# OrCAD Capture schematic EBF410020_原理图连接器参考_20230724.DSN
size A3; title: 野火_ZYNQ7010核心板_原理图; rev: V1.1; note: BTB Connector; note: https://yehuosm.tmall.com
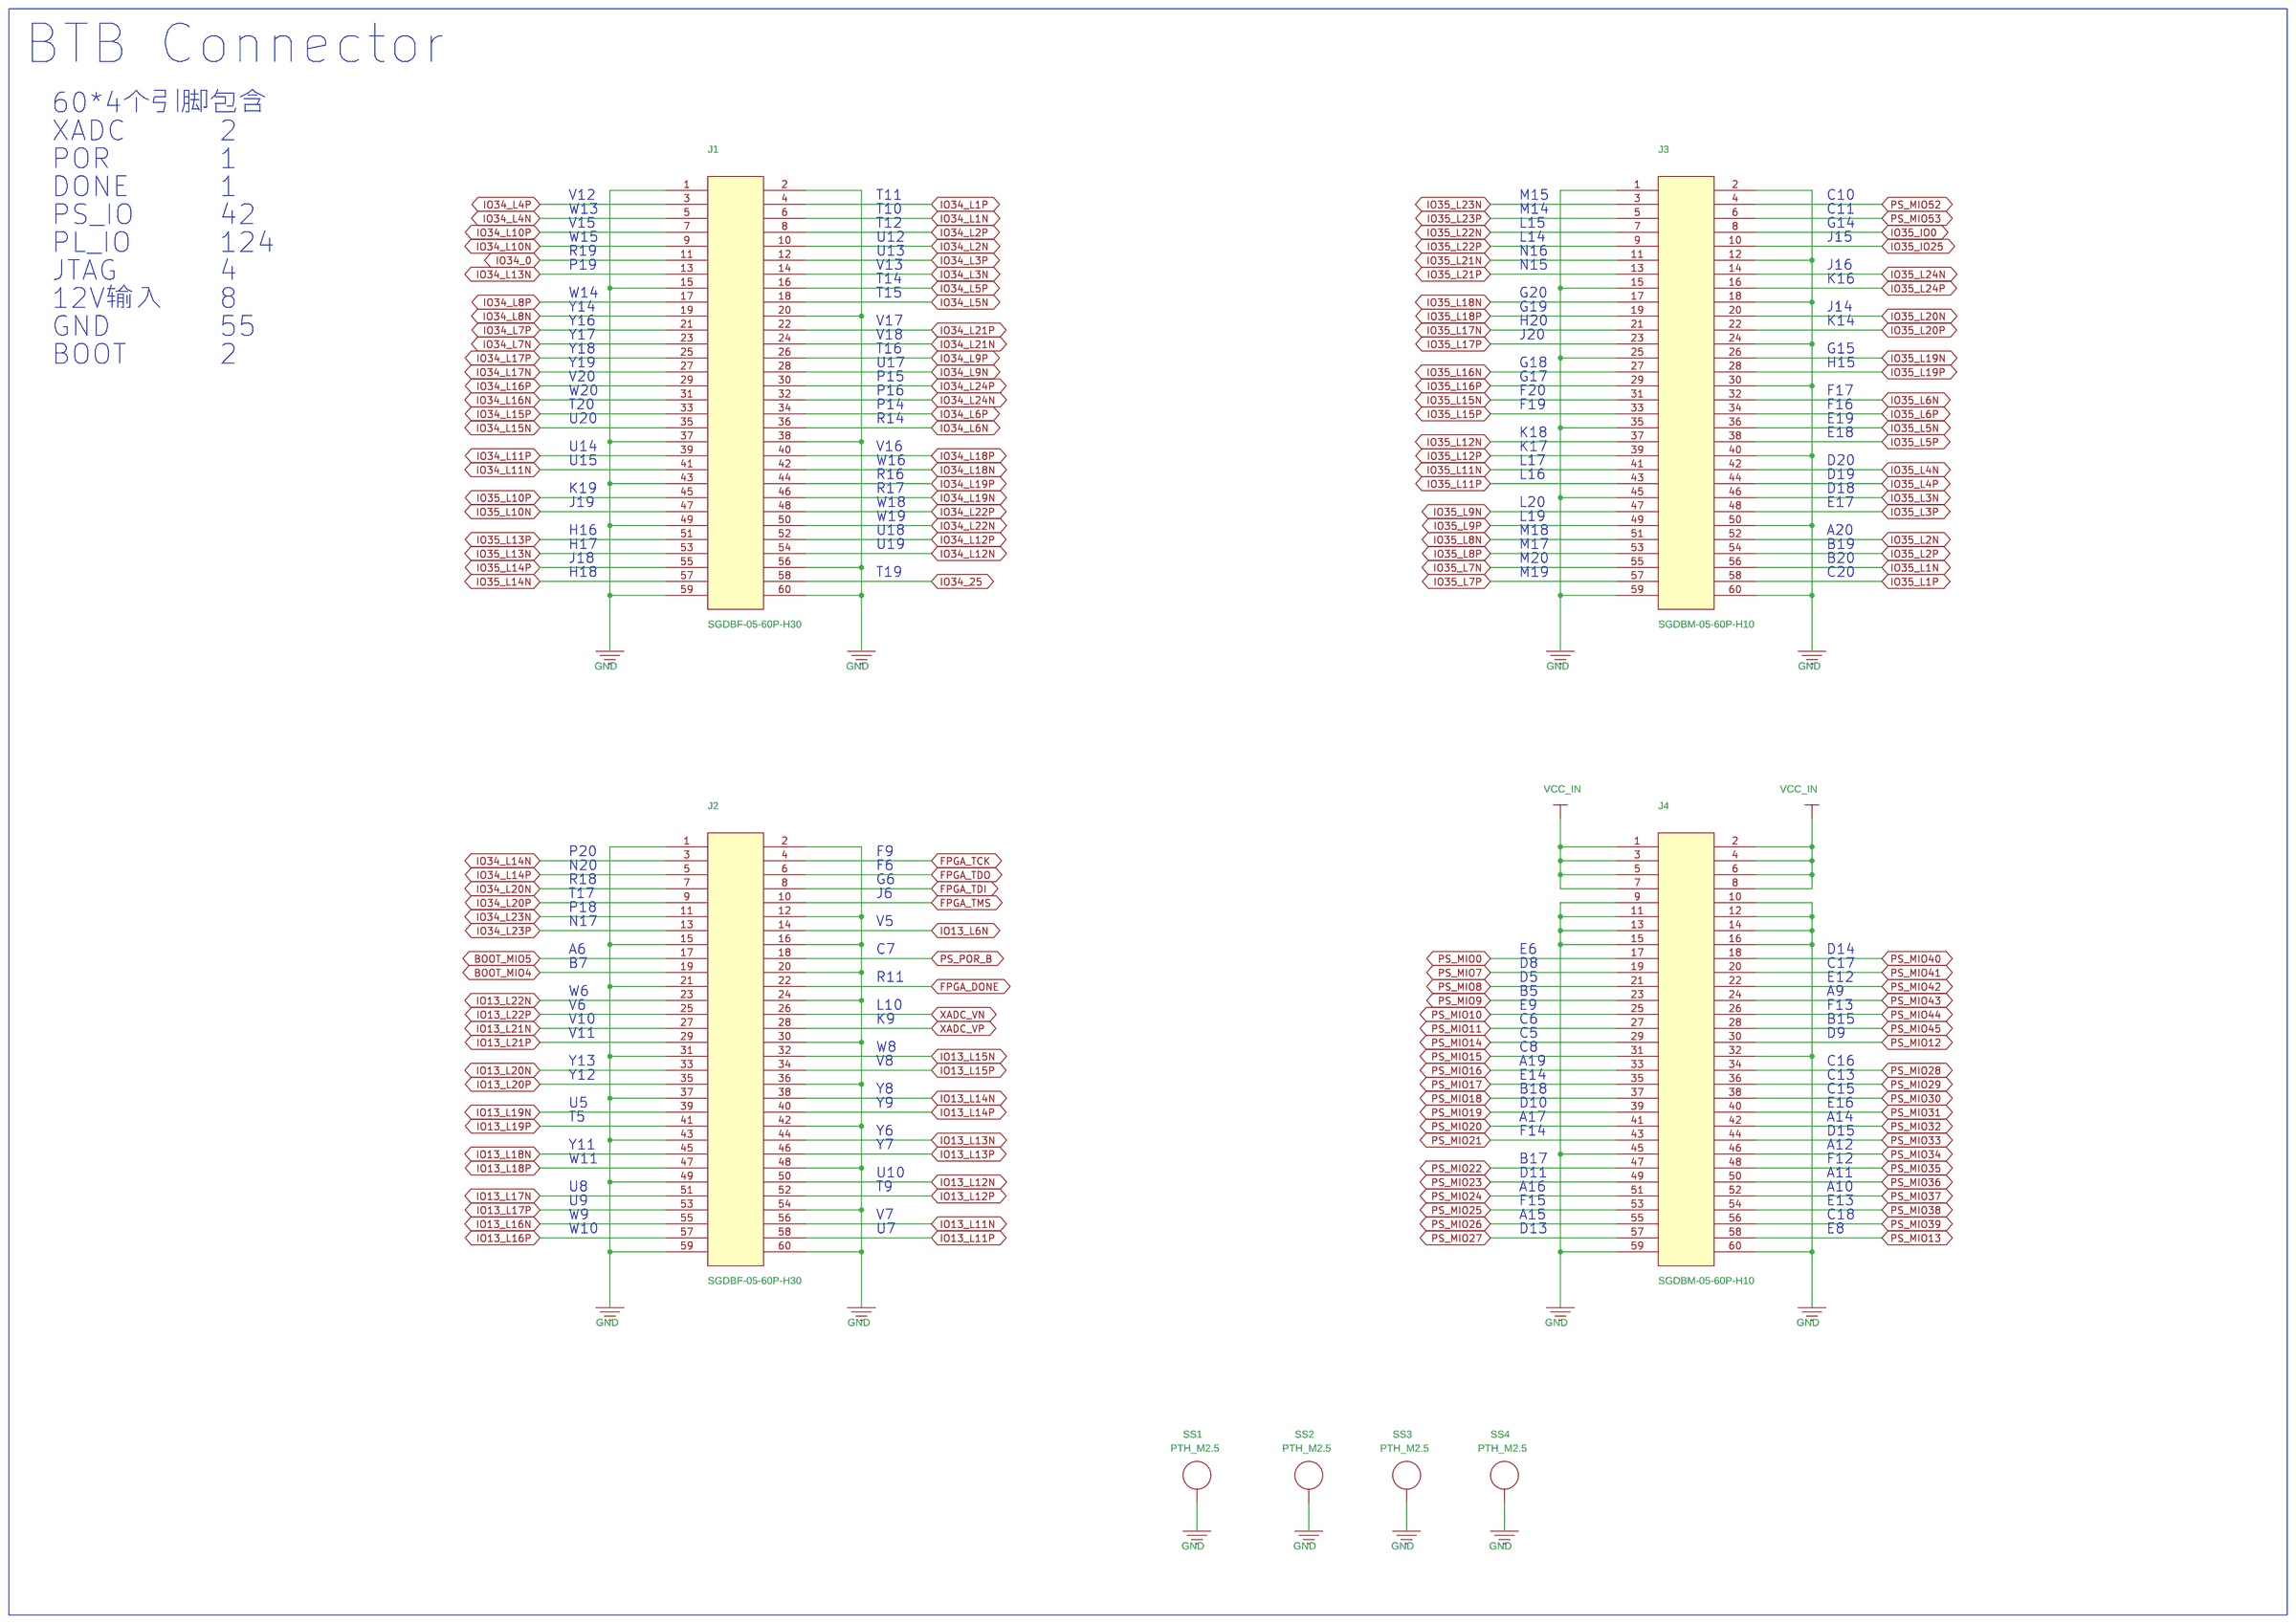
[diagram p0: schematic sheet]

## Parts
J1  SGDBF-05-60P-H30  [BTB_2X30_0P5_F]
J2  SGDBF-05-60P-H30  [BTB_2X30_0P5_F]
J3  SGDBM-05-60P-H10  [BTB_2x30_0p5_M]
J4  SGDBM-05-60P-H10  [BTB_2x30_0p5_M]
SS1  PTH_M2.5  [SMTSO-M2r5-Hole]
SS2  PTH_M2.5  [SMTSO-M2r5-Hole]
SS3  PTH_M2.5  [SMTSO-M2r5-Hole]
SS4  PTH_M2.5  [SMTSO-M2r5-Hole]

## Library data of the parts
J1 J2 = 2X30PIN: 备注: 赛灵思ZYNQ7010，GD32系列板卡; 规格: 0.5mm BTB母座2*30P 双槽 立贴式 合高4.0mm; 规格书: 山谷道_双槽板对板公母立贴式0_5mm.pdf; 类别: BTB连接器; 品牌: 山谷道; 生命周期: 量产; 条码: EBFCIS230705115421
J3 J4 = 2X30PIN: 备注: 赛灵思ZYNQ7010，GD32系列BTB核心板; 规格: 0.5mm BTB公座2*30P 双槽 立贴式 合高4.0mm; 规格书: 山谷道_双槽板对板公母立贴式0_5mm.pdf; 类别: BTB连接器; 品牌: 山谷道; 生命周期: 量产; 条码: EBFCIS230705120008
SS1-SS4 = SPACER: 规格: M2.5螺丝孔 有铜 搭配SMTSO25贴片螺母使用; 类别: M2.5螺丝孔; 品牌: 野火; 条码: EBFCIS230202105906

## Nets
GND: J1.1 J1.2 J1.15 J1.20 J1.37 J1.38 J1.43 J1.49 J1.56 J1.59 J1.60 J2.1 J2.2 J2.12 J2.15 J2.16 J2.20 J2.21 J2.24 J2.30 J2.31 J2.36 J2.37 J2.42 J2.43 J2.48 J2.49 J2.54 J2.59 J2.60 J3.1 J3.2 J3.12 J3.15 J3.18 J3.24 J3.25 J3.30 J3.35 J3.40 J3.45 J3.50 J3.59 J3.60 J4.9 J4.10 J4.11 J4.12 J4.13 J4.14 J4.15 J4.16 J4.32 J4.45 J4.59 J4.60 SS1.1(NC) SS2.1(NC) SS3.1(NC) SS4.1(NC)
VCC_IN: J4.1 J4.2 J4.3 J4.4 J4.5 J4.6 J4.7 J4.8
BOOT_MIO4: J2.19
BOOT_MIO5: J2.17
FPGA_DONE: J2.22
FPGA_TCK: J2.4
FPGA_TDI: J2.8
FPGA_TDO: J2.6
FPGA_TMS: J2.10
IO13_L6N: J2.14
IO13_L11N: J2.56
IO13_L11P: J2.58
IO13_L12N: J2.50
IO13_L12P: J2.52
IO13_L13N: J2.44
IO13_L13P: J2.46
IO13_L14N: J2.38
IO13_L14P: J2.40
IO13_L15N: J2.32
IO13_L15P: J2.34
IO13_L16N: J2.55
IO13_L16P: J2.57
IO13_L17N: J2.51
IO13_L17P: J2.53
IO13_L18N: J2.45
IO13_L18P: J2.47
IO13_L19N: J2.39
IO13_L19P: J2.41
IO13_L20N: J2.33
IO13_L20P: J2.35
IO13_L21N: J2.27
IO13_L21P: J2.29
IO13_L22N: J2.23
IO13_L22P: J2.25
IO34_0: J1.11
IO34_25: J1.58
IO34_L1N: J1.6
IO34_L1P: J1.4
IO34_L2N: J1.10
IO34_L2P: J1.8
IO34_L3N: J1.14
IO34_L3P: J1.12
IO34_L4N: J1.5
IO34_L4P: J1.3
IO34_L5N: J1.18
IO34_L5P: J1.16
IO34_L6N: J1.36
IO34_L6P: J1.34
IO34_L7N: J1.23
IO34_L7P: J1.21
IO34_L8N: J1.19
IO34_L8P: J1.17
IO34_L9N: J1.28
IO34_L9P: J1.26
IO34_L10N: J1.9
IO34_L10P: J1.7
IO34_L11N: J1.41
IO34_L11P: J1.39
IO34_L12N: J1.54
IO34_L12P: J1.52
IO34_L13N: J1.13
IO34_L14N: J2.3
IO34_L14P: J2.5
IO34_L15N: J1.35
IO34_L15P: J1.33
IO34_L16N: J1.31
IO34_L16P: J1.29
IO34_L17N: J1.27
IO34_L17P: J1.25
IO34_L18N: J1.42
IO34_L18P: J1.40
IO34_L19N: J1.46
IO34_L19P: J1.44
IO34_L20N: J2.7
IO34_L20P: J2.9
IO34_L21N: J1.24
IO34_L21P: J1.22
IO34_L22N: J1.50
IO34_L22P: J1.48
IO34_L23N: J2.11
IO34_L23P: J2.13
IO34_L24N: J1.32
IO34_L24P: J1.30
IO35_IO0: J3.8
IO35_IO25: J3.10
IO35_L1N: J3.56
IO35_L1P: J3.58
IO35_L2N: J3.52
IO35_L2P: J3.54
IO35_L3N: J3.46
IO35_L3P: J3.48
IO35_L4N: J3.42
IO35_L4P: J3.44
IO35_L5N: J3.36
IO35_L5P: J3.38
IO35_L6N: J3.32
IO35_L6P: J3.34
IO35_L7N: J3.55
IO35_L7P: J3.57
IO35_L8N: J3.51
IO35_L8P: J3.53
IO35_L9N: J3.47
IO35_L9P: J3.49
IO35_L10N: J1.47
IO35_L10P: J1.45
IO35_L11N: J3.41
IO35_L11P: J3.43
IO35_L12N: J3.37
IO35_L12P: J3.39
IO35_L13N: J1.53
IO35_L13P: J1.51
IO35_L14N: J1.57
IO35_L14P: J1.55
IO35_L15N: J3.31
IO35_L15P: J3.33
IO35_L16N: J3.27
IO35_L16P: J3.29
IO35_L17N: J3.21
IO35_L17P: J3.23
IO35_L18N: J3.17
IO35_L18P: J3.19
IO35_L19N: J3.26
IO35_L19P: J3.28
IO35_L20N: J3.20
IO35_L20P: J3.22
IO35_L21N: J3.11
IO35_L21P: J3.13
IO35_L22N: J3.7
IO35_L22P: J3.9
IO35_L23N: J3.3
IO35_L23P: J3.5
IO35_L24N: J3.14
IO35_L24P: J3.16
PS_MIO0: J4.17
PS_MIO7: J4.19
PS_MIO8: J4.21
PS_MIO9: J4.23
PS_MIO10: J4.25
PS_MIO11: J4.27
PS_MIO12: J4.30
PS_MIO13: J4.58
PS_MIO14: J4.29
PS_MIO15: J4.31
PS_MIO16: J4.33
PS_MIO17: J4.35
PS_MIO18: J4.37
PS_MIO19: J4.39
PS_MIO20: J4.41
PS_MIO21: J4.43
PS_MIO22: J4.47
PS_MIO23: J4.49
PS_MIO24: J4.51
PS_MIO25: J4.53
PS_MIO26: J4.55
PS_MIO27: J4.57
PS_MIO28: J4.34
PS_MIO29: J4.36
PS_MIO30: J4.38
PS_MIO31: J4.40
PS_MIO32: J4.42
PS_MIO33: J4.44
PS_MIO34: J4.46
PS_MIO35: J4.48
PS_MIO36: J4.50
PS_MIO37: J4.52
PS_MIO38: J4.54
PS_MIO39: J4.56
PS_MIO40: J4.18
PS_MIO41: J4.20
PS_MIO42: J4.22
PS_MIO43: J4.24
PS_MIO44: J4.26
PS_MIO45: J4.28
PS_MIO52: J3.4
PS_MIO53: J3.6
PS_POR_B: J2.18
XADC_VN: J2.26
XADC_VP: J2.28

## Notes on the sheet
- BTB Connector
- 60*4个引脚包含
- XADC
- 2
- POR
- 1
- DONE
- 1
- V12
- T11
- M15
- C10
- PS_IO
- 42
- W13
- T10
- M14
- C11
- V15
- T12
- L15
- G14
- PL_IO
- 124
- R19
- W15
- U12
- U13
- L14
- N16
- J15
- JTAG
- 4
- P19
- V13
- N15
- J16
- T14
- K16
- 12V输入
- 8
- W14
- T15
- G20
- Y14
- G19
- J14
- GND
- 55
- Y16
- V17
- H20
- K14
- BOOT
- 2
- Y17
- Y18
- T16
- V18
- J20
- G15
- Y19
- U17
- G18
- H15
- V20
- P15
- G17
- W20
- P16
- F20
- F17
- T20
- P14
- F19
- F16
- U20
- R14
- K18
- E18
- E19
- U14
- V16
- K17
- U15
- W16
- L17
- D20
- R16
- L16
- D19
- K19
- R17
- D18
- J19
- W18
- L20
- E17
- H16
- U18
- W19
- L19
- M18
- A20
- H17
- U19
- M17
- B19
- J18
- M20
- B20
- H18
- T19
- M19
- C20
- P20
- F9
- N20
- F6
- R18
- T17
- G6
- J6
- P18
- N17
- V5
- A6
- C7
- E6
- D14
- B7
- D8
- C17
- W6
- R11
- B5
- D5
- A9
- E12
- V6
- L10
- E9
- F13
- V10
- K9
- C6
- B15
- V11
- C5
- D9
- W8
- C8
- Y12
- Y13
- V8
- A19
- E14
- C13
- C16
- Y8
- B18
- C15
- U5
- Y9
- D10
- E16
- T5
- A17
- A14
- Y6
- F14
- D15
- Y11
- Y7
- A12
- W11
- U10
- B17
- D11
- A11
- F12
- U8
- T9
- A16
- A10
- U9
- F15
- E13
- W9
- V7
- A15
- C18
- W10
- U7
- D13
- E8
